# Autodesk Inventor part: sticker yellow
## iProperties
Shininess: 64.0
Length Units: 11269
Angle Units: 11279
Time Units: 11290
Mass Units: 11283
Length Display Precision: 3
Angle Display Precision: 2
Compacted: True
Part Number: sticker yellow
Document SubType Name: Modeling
Created: 2004-10
Material: Standard
Designer: W. Holzwarth
Manufacturer: Standard
Standards Organization: Custom
Density: 0.0
Volumn: 0.0
Area: 0.0
PropertySet Name: Model Information
Control State: 0
Master: False
Checked Out: False
Author: W. Holzwarth
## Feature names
1. Basis1
